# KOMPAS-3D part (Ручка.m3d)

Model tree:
1. Эскиз:1
2. Эскиз:2
3. Кинематическая операция:1
     Толщина стенки 1 = 1; Толщина стенки 2 = 1
4. Эскиз:3
5. Операция выдавливания:1
     Расстояние 1 = 0.5; Расстояние 2 = 0.5
6. Скругление:1
     Радиус = 0.5
7. Смещенная плоскость:1
     Расстояние = 13
8. Эскиз:4
9. Вырезать элемент выдавливания:1
     Расстояние 2 = 2; Расстояние 1 = 25
10. Эскиз:5
11. Вырезать элемент выдавливания:2
     Расстояние 2 = 18; Расстояние 1 = 18
12. Условное изображение резьбы:1
     Длина резьбы = 17; Шаг резьбы = 1; Номинальный диаметр резьбы = 10
13. Фаска:1
     Угол = 45; Длина 1 = 1; Длина 2 = 1
14. Фаска:2
     Угол = 45; Длина 1 = 1; Длина 2 = 1

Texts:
  Фторопласт-4  ГОСТ 10007-80 Е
